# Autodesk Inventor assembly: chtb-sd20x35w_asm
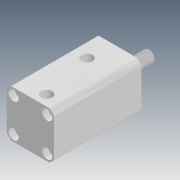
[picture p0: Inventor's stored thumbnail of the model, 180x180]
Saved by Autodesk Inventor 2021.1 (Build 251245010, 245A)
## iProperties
Company: Microsoft
Created: 2018-05
Part Number: chtb-sd20x35w_asm
Description: STEP AP214
Document SubType Name: Assembly
Designer: user
Title: chtb-sd20x35w_asm.STEP
Author: Windows
Revision Number: ÈÎºÎ
Sending System: SolidWorks 2015
Preprocessor: SwSTEP 2.0
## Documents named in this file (4)
- D:\Vault_2016\Projekty\Clamptek\Hydraulic\CHTB\CHTB-20\Inventor\CHTB-SD20x35W\chtb-sd20x35w_asm.iam
- D:\Vault_2016\Projekty\Clamptek\Hydraulic\CHTB\CHTB-20\Inventor\CHTB-SD20x35W\CHTB-SD20X35NBT.ipt
- D:\Vault_2016\Projekty\Clamptek\Hydraulic\CHTB\CHTB-20\Inventor\CHTB-SD20x35W\CHTB-SD20X35WHSG.ipt
- D:\Vault_2016\Projekty\Clamptek\Hydraulic\CHTB\CHTB-20\Inventor\CHTB-SD20x35W\QG.ipt
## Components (3 placed, 3 different names)
1. CHTB-SD20X35NBT_1
2. CHTB-SD20X35WHSG_2
3. QG_3
